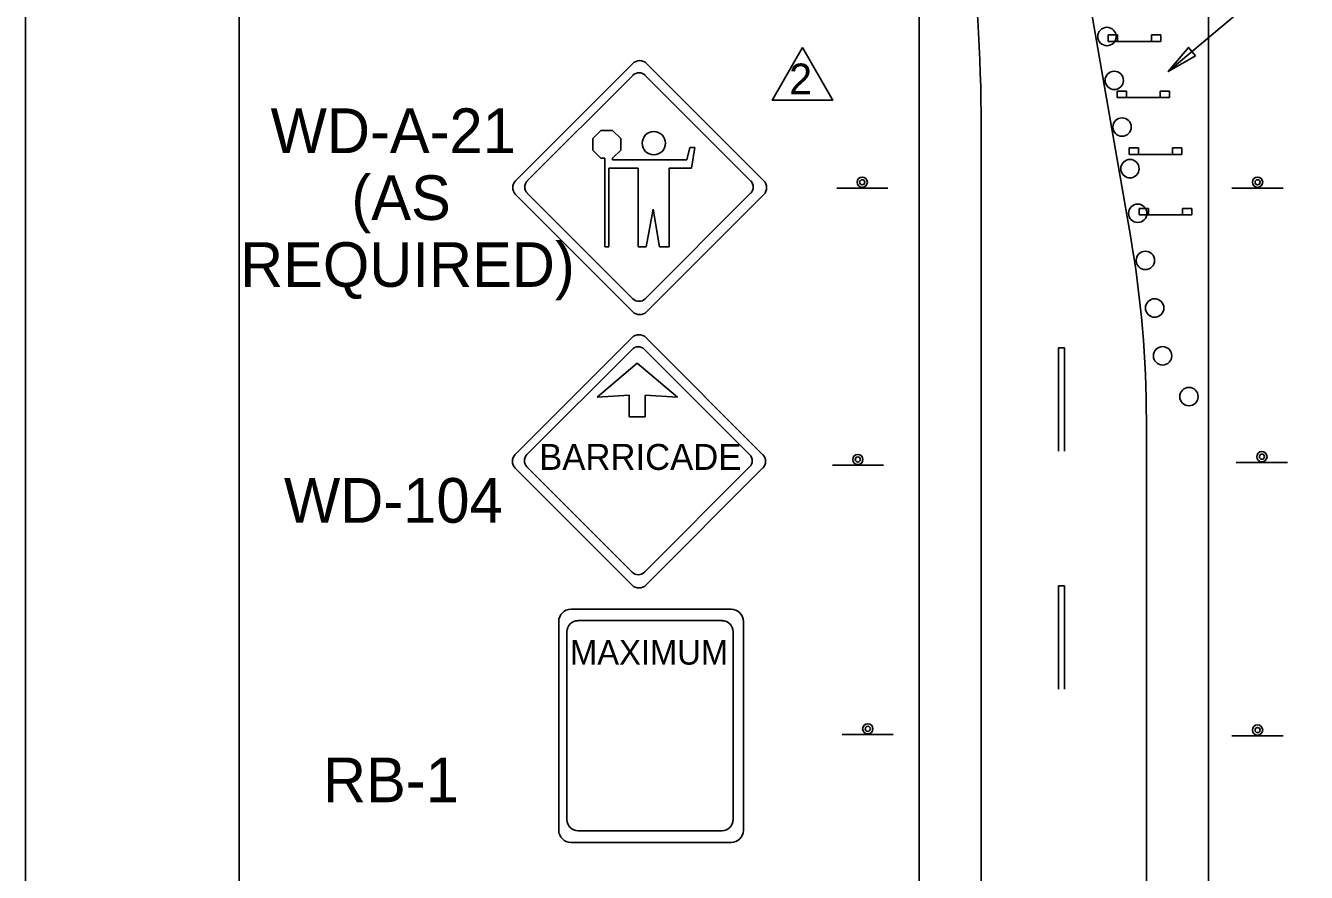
# Model space of a CAD drawing. Extents: x 2179 to 2395, y 134 to 413.
# Drawn here: x 2178.7 to 2238.8, y 254.8 to 294.5 of the extents above; entities that cross this region are included whole.
import ezdxf

# ---------------------------------------------------------------- set-up
doc = ezdxf.new("R2010")
doc.units = 0
for name, color, linetype in [('Level 1', 7, 'Continuous'), ('Level 10', 7, 'Continuous'), ('Level 44', 7, 'Continuous'), ('Level 5', 7, 'Continuous'), ('Level 60', 7, 'Continuous')]:
    doc.layers.add(name, color=color, linetype=linetype)

msp = doc.modelspace()

# ---------------------------------------------------------------- linework, layer by layer
at = {"layer": 'Level 1'}
for p, q in [((2205.706, 289.596), (2205.323, 289.213)), ((2206.249, 289.596), (2205.706, 289.596)), ((2206.632, 289.213), (2206.249, 289.596)), ((2205.323, 289.213), (2205.323, 288.67)), ((2205.323, 288.67), (2205.706, 288.287)), ((2206.249, 288.287), (2206.632, 288.67)), ((2206.632, 288.67), (2206.632, 289.213)), ((2209.865, 288.799), (2209.725, 288.216)), ((2210.109, 288.799), (2209.865, 288.799)), ((2209.95, 287.825), (2210.109, 288.799)), ((2205.706, 288.287), (2205.88, 288.287)), ((2205.88, 288.287), (2205.88, 284.133)), ((2206.249, 288.216), (2206.249, 288.287)), ((2209.725, 288.216), (2206.249, 288.216)), ((2206.07, 284.133), (2206.07, 287.825)), ((2206.07, 287.825), (2207.453, 287.825)), ((2207.453, 287.825), (2207.453, 284.133)), ((2208.902, 284.133), (2208.902, 287.825)), ((2208.902, 287.825), (2209.95, 287.825)), ((2207.82, 284.133), (2208.147, 285.902)), ((2208.147, 285.902), (2208.456, 284.133)), ((2205.88, 284.133), (2206.07, 284.133)), ((2207.453, 284.133), (2207.82, 284.133)), ((2208.456, 284.133), (2208.902, 284.133)), ((2227.137, 279.411), (2227.137, 274.573)), ((2227.427, 279.411), (2227.137, 279.411)), ((2227.427, 274.573), (2227.427, 279.411)), ((2227.137, 268.27), (2227.137, 263.432)), ((2227.427, 268.27), (2227.137, 268.27)), ((2227.137, 268.27), (2227.137, 263.432)), ((2227.427, 268.27), (2227.137, 268.27)), ((2227.427, 263.432), (2227.427, 268.27)), ((2227.427, 263.432), (2227.427, 268.27))]:
    msp.add_line(p, q, dxfattribs=at)
for points in [[(2394.748, 412.757), (2178.748, 412.757), (2178.748, 133.757), (2394.748, 133.757)], [(2375.622, 401.948), (2188.748, 401.948), (2188.748, 144.566), (2375.622, 144.566)]]:
    msp.add_lwpolyline(points, close=True, dxfattribs=at)
msp.add_circle((2208.182, 288.994), 0.544, dxfattribs=at)
at = {"layer": 'Level 10'}
for p, q in [((2234.164, 223.027), (2234.164, 325.439)), ((2225.504, 313.525), (2230.526, 284.563)), ((2220.617, 223.004), (2220.617, 307.66)), ((2232.288, 292.347), (2239.364, 298.329)), ((2223.52, 223.009), (2223.52, 289.755)), ((2231.261, 223.022), (2231.261, 276.021))]:
    msp.add_line(p, q, dxfattribs=at)
msp.add_lwpolyline([(2233.561, 293.09), (2232.288, 292.347), (2233.233, 293.478)], close=True, dxfattribs=at)
for centre in [(2229.413, 293.99), (2229.758, 291.937), (2230.122, 289.75), (2230.493, 287.801), (2230.858, 285.711), (2231.214, 283.503), (2231.649, 281.276), (2232.019, 279.037), (2233.257, 277.129)]:
    msp.add_circle(centre, 0.431, dxfattribs=at)
for centre, radius, end in [((2143.52, 289.755), 80, 7.19647), ((2181.261, 276.021), 50, 9.83701)]:
    msp.add_arc(centre, radius, 0, end, dxfattribs=at)
at = {"layer": 'Level 44'}
for p, q in [((2207.198, 292.725), (2201.704, 287.239)), ((2213.332, 287.239), (2207.847, 292.725)), ((2202.254, 287.235), (2207.198, 292.172)), ((2207.782, 292.172), (2212.72, 287.235)), ((2219.15, 286.895), (2216.754, 286.895)), ((2235.267, 286.895), (2237.663, 286.895)), ((2201.704, 286.588), (2207.198, 281.097)), ((2201.709, 286.588), (2201.704, 286.588)), ((2207.198, 281.708), (2202.254, 286.648)), ((2212.72, 286.648), (2207.782, 281.708)), ((2207.847, 281.097), (2213.332, 286.588)), ((2207.164, 279.89), (2201.686, 274.421)), ((2213.28, 274.421), (2207.811, 279.89)), ((2202.234, 274.416), (2207.164, 279.339)), ((2207.746, 279.339), (2212.67, 274.416)), ((2207.405, 278.693), (2205.523, 277.106)), ((2209.287, 277.106), (2207.405, 278.693)), ((2205.523, 277.106), (2207.027, 277.187)), ((2207.027, 277.187), (2207.027, 276.183)), ((2207.782, 276.183), (2207.782, 277.187)), ((2207.782, 277.187), (2209.287, 277.106)), ((2207.027, 276.183), (2207.777, 276.183)), ((2201.686, 273.771), (2207.164, 268.296)), ((2201.691, 273.771), (2201.686, 273.771)), ((2207.164, 268.905), (2202.234, 273.832)), ((2212.67, 273.832), (2207.746, 268.905)), ((2207.811, 268.296), (2213.28, 273.771)), ((2218.946, 273.914), (2216.549, 273.914)), ((2235.471, 274.045), (2237.867, 274.045)), ((2204.305, 267.174), (2211.801, 267.174)), ((2203.727, 256.825), (2203.727, 266.595)), ((2204.633, 266.635), (2211.379, 266.635)), ((2212.38, 266.595), (2212.38, 256.825)), ((2204.113, 257.319), (2204.113, 266.114)), ((2211.9, 266.114), (2211.9, 257.319)), ((2217.003, 261.3), (2219.4, 261.3)), ((2235.267, 261.244), (2237.663, 261.244)), ((2204.113, 257.318), (2204.113, 257.319)), ((2203.727, 256.822), (2203.727, 256.825)), ((2211.801, 256.244), (2204.305, 256.244)), ((2211.379, 256.798), (2204.633, 256.798))]:
    msp.add_line(p, q, dxfattribs=at)
for centre, radius in [((2217.947, 287.164), 0.24), ((2217.947, 287.164), 0.12), ((2236.471, 287.164), 0.24), ((2236.471, 287.164), 0.12), ((2217.742, 274.183), 0.24), ((2217.742, 274.183), 0.12), ((2236.675, 274.314), 0.24), ((2236.675, 274.314), 0.12), ((2218.207, 261.569), 0.24), ((2218.207, 261.569), 0.12), ((2236.471, 261.513), 0.24), ((2236.471, 261.513), 0.12)]:
    msp.add_circle(centre, radius, dxfattribs=at)
for centre, radius, start, end in [((2207.521, 292.402), 0.459, 45, 135), ((2207.489, 291.881), 0.413, 45, 135), ((2202.033, 286.913), 0.459, 135, 224.99999), ((2202.549, 286.941), 0.413, 135, 224.99999), ((2212.429, 286.941), 0.413, 315, 45), ((2213.01, 286.913), 0.459, 315, 45), ((2207.489, 282.002), 0.413, 225, 315), ((2207.521, 281.425), 0.459, 225, 315), ((2207.486, 279.568), 0.458, 45, 135), ((2207.454, 279.049), 0.412, 45, 135), ((2202.014, 274.096), 0.458, 135, 224.99999), ((2202.529, 274.124), 0.412, 135, 224.99999), ((2212.379, 274.124), 0.412, 315, 45), ((2212.959, 274.096), 0.458, 315, 45), ((2207.454, 269.198), 0.412, 225, 315), ((2207.486, 268.623), 0.458, 225, 315), ((2204.305, 266.595), 0.578, 90, 179.99999), ((2211.8, 266.595), 0.578, 359.99999, 89.99999), ((2204.633, 266.113), 0.52, 90, 179.99999), ((2211.378, 266.113), 0.52, 359.99999, 89.99999), ((2204.633, 257.318), 0.52, 180, 269.99999), ((2211.378, 257.318), 0.52, 270, 359.99999), ((2204.305, 256.823), 0.578, 180, 269.99999), ((2211.8, 256.823), 0.578, 270, 359.99999)]:
    msp.add_arc(centre, radius, start, end, dxfattribs=at)
at = {"layer": 'Level 5'}
for p, q in [((2229.914, 294.069), (2229.478, 294.069)), ((2229.478, 294.069), (2229.478, 293.763)), ((2229.913, 293.764), (2229.914, 294.069)), ((2231.94, 294.069), (2231.505, 294.069)), ((2231.505, 294.069), (2231.505, 293.763)), ((2231.94, 293.763), (2231.94, 294.069)), ((2229.478, 293.763), (2231.94, 293.763)), ((2230.322, 291.436), (2229.886, 291.436)), ((2229.886, 291.436), (2229.886, 291.129)), ((2229.886, 291.129), (2232.348, 291.13)), ((2230.322, 291.13), (2230.322, 291.436)), ((2232.348, 291.436), (2231.913, 291.436)), ((2231.913, 291.436), (2231.913, 291.13)), ((2232.348, 291.13), (2232.348, 291.436)), ((2230.889, 288.771), (2230.453, 288.771)), ((2230.453, 288.771), (2230.453, 288.465)), ((2230.889, 288.466), (2230.889, 288.771)), ((2232.915, 288.771), (2232.48, 288.771)), ((2232.48, 288.771), (2232.48, 288.465)), ((2232.915, 288.465), (2232.915, 288.771)), ((2230.453, 288.465), (2232.915, 288.465)), ((2231.36, 285.942), (2230.925, 285.942)), ((2230.925, 285.942), (2230.925, 285.636)), ((2231.36, 285.637), (2231.36, 285.942)), ((2233.387, 285.942), (2232.951, 285.943)), ((2232.951, 285.942), (2232.951, 285.637)), ((2233.387, 285.637), (2233.387, 285.942)), ((2230.925, 285.636), (2233.387, 285.637))]:
    msp.add_line(p, q, dxfattribs=at)
at = {"layer": 'Level 60'}
for points in [[(2215.149, 293.476), (2213.756, 291.051)], [(2216.543, 291.051), (2215.149, 293.476)], [(2213.756, 291.051), (2213.73, 291.006), (2216.569, 291.006), (2216.543, 291.051)]]:
    msp.add_lwpolyline(points, dxfattribs=at)

# ---------------------------------------------------------------- texts
at = {"layer": 'Level 10'}
for s, p in [('WD-A-21', (2190.227, 288.534)), ('(AS ', (2194.012, 285.4)), ('REQUIRED)', (2188.795, 282.266)), ('WD-104', (2190.853, 271.221)), ('RB-1', (2192.68, 258.131))]:
    msp.add_text(s, height=2.09, dxfattribs=at).set_placement(p)
at = {"layer": 'Level 44'}
for s, height, p in [('BARRICADE', 1.2144, (2202.811, 273.695)), ('MAXIMUM', 1.1467, (2204.254, 264.576))]:
    msp.add_text(s, height=height, rotation=360, dxfattribs=at).set_placement(p)
at = {"layer": 'Level 60'}
msp.add_text('2', height=1.448, rotation=360, dxfattribs=at).set_placement((2214.522, 291.275))

doc.saveas('drawing.dxf')
